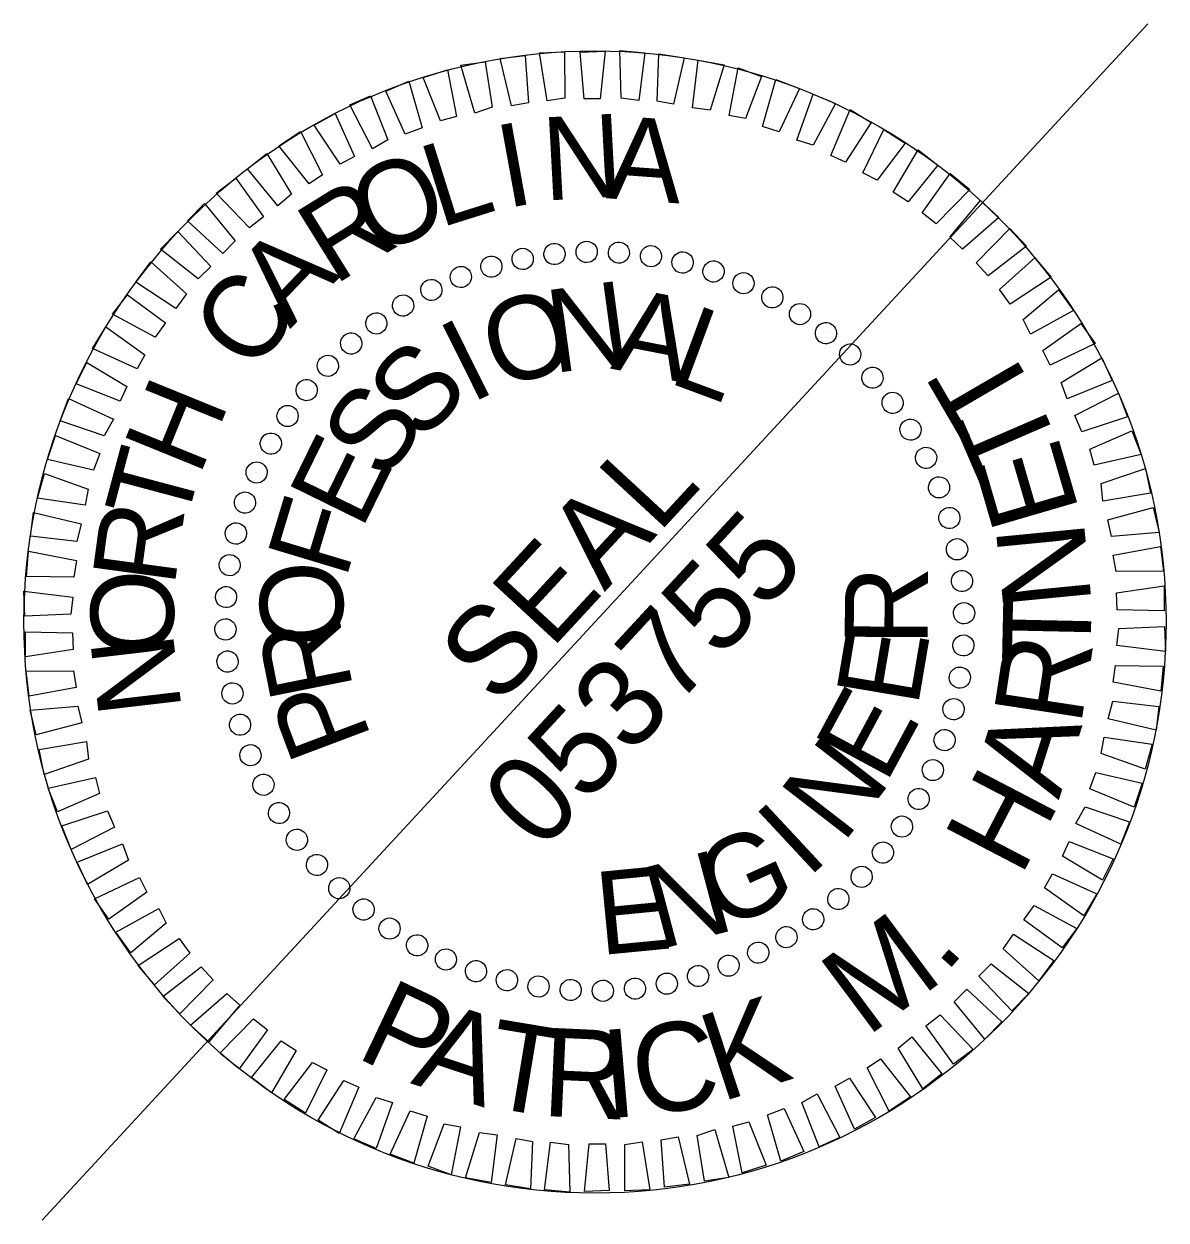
# Model space of a CAD drawing. Extents: x 1768274 to 1769121, y 999922 to 1000687.
# Drawn here: x 1769002.478 to 1769003.66, y 1000309.793 to 1000311.03 of the extents above; entities that cross this region are included whole.
import ezdxf

# ---------------------------------------------------------------- set-up
doc = ezdxf.new("R2010")
doc.units = 0
doc.layers.add('E_NCDOT_Terrain_Model_Contour_Imported', color=7, linetype='Continuous')
doc.layers.add('E_NCDOT_Terrain_Model_Void', color=7, linetype='Continuous')

msp = doc.modelspace()

# ---------------------------------------------------------------- linework, layer by layer
at = {"layer": 'E_NCDOT_Terrain_Model_Contour_Imported'}
msp.add_line((1769003.6407, 1000311.0298), (1769002.4971, 1000309.7927), dxfattribs=at)
msp.add_circle((1769003.0689, 1000310.4113), 0.5907, dxfattribs=at)
at = {"layer": 'E_NCDOT_Terrain_Model_Void'}
for p, q in [((1769002.9941, 1000310.7869), (1769002.9941, 1000310.7869)), ((1769003.0273, 1000310.7926), (1769003.0273, 1000310.7926)), ((1769003.0601, 1000310.7944), (1769003.0601, 1000310.7944)), ((1769003.0941, 1000310.7941), (1769003.0941, 1000310.7941)), ((1769003.1266, 1000310.79), (1769003.1266, 1000310.79)), ((1769003.1597, 1000310.7832), (1769003.1597, 1000310.7832)), ((1769002.9615, 1000310.7797), (1769002.9615, 1000310.7797)), ((1769003.1919, 1000310.7742), (1769003.1919, 1000310.7742)), ((1769002.9301, 1000310.7683), (1769002.9301, 1000310.7683)), ((1769003.2225, 1000310.7625), (1769003.2225, 1000310.7625)), ((1769002.8993, 1000310.7552), (1769002.8993, 1000310.7552)), ((1769003.2522, 1000310.7475), (1769003.2522, 1000310.7475)), ((1769002.8698, 1000310.7389), (1769002.8698, 1000310.7389)), ((1769003.281, 1000310.7292), (1769003.281, 1000310.7292)), ((1769002.843, 1000310.7201), (1769002.843, 1000310.7201)), ((1769003.3081, 1000310.7103), (1769003.3081, 1000310.7103)), ((1769002.8169, 1000310.6997), (1769002.8169, 1000310.6997)), ((1769003.3333, 1000310.6881), (1769003.3333, 1000310.6881)), ((1769002.7925, 1000310.6766), (1769002.7925, 1000310.6766)), ((1769003.3563, 1000310.6637), (1769003.3563, 1000310.6637)), ((1769002.7703, 1000310.6515), (1769002.7703, 1000310.6515)), ((1769003.3768, 1000310.6376), (1769003.3768, 1000310.6376)), ((1769002.7514, 1000310.6243), (1769002.7514, 1000310.6243)), ((1769003.3956, 1000310.6108), (1769003.3956, 1000310.6108)), ((1769002.7331, 1000310.5955), (1769002.7331, 1000310.5955)), ((1769003.4119, 1000310.5813), (1769003.4119, 1000310.5813)), ((1769002.7181, 1000310.5658), (1769002.7181, 1000310.5658)), ((1769003.4249, 1000310.5505), (1769003.4249, 1000310.5505)), ((1769002.7064, 1000310.5352), (1769002.7064, 1000310.5352)), ((1769003.4364, 1000310.5192), (1769003.4364, 1000310.5192)), ((1769002.6974, 1000310.503), (1769002.6974, 1000310.503)), ((1769003.4436, 1000310.4865), (1769003.4436, 1000310.4865)), ((1769002.6906, 1000310.4699), (1769002.6906, 1000310.4699)), ((1769003.4492, 1000310.4533), (1769003.4492, 1000310.4533)), ((1769002.6865, 1000310.4374), (1769002.6865, 1000310.4374)), ((1769003.4511, 1000310.4205), (1769003.4511, 1000310.4205)), ((1769002.6862, 1000310.4034), (1769002.6862, 1000310.4034)), ((1769003.0686, 1000310.412), (1769003.0686, 1000310.412)), ((1769003.4508, 1000310.3866), (1769003.4508, 1000310.3866)), ((1769002.688, 1000310.3706), (1769002.688, 1000310.3706)), ((1769003.4467, 1000310.354), (1769003.4467, 1000310.354)), ((1769002.6937, 1000310.3374), (1769002.6937, 1000310.3374)), ((1769003.4399, 1000310.3209), (1769003.4399, 1000310.3209)), ((1769002.7009, 1000310.3048), (1769002.7009, 1000310.3048)), ((1769003.4309, 1000310.2887), (1769003.4309, 1000310.2887)), ((1769002.7124, 1000310.2734), (1769002.7124, 1000310.2734)), ((1769003.4192, 1000310.2581), (1769003.4192, 1000310.2581)), ((1769002.7254, 1000310.2427), (1769002.7254, 1000310.2427)), ((1769003.4042, 1000310.2284), (1769003.4042, 1000310.2284)), ((1769002.7417, 1000310.2131), (1769002.7417, 1000310.2131)), ((1769003.3859, 1000310.1996), (1769003.3859, 1000310.1996)), ((1769002.7605, 1000310.1864), (1769002.7605, 1000310.1864)), ((1769003.367, 1000310.1725), (1769003.367, 1000310.1725)), ((1769002.781, 1000310.1602), (1769002.781, 1000310.1602)), ((1769003.3448, 1000310.1473), (1769003.3448, 1000310.1473)), ((1769002.804, 1000310.1358), (1769002.804, 1000310.1358)), ((1769003.3204, 1000310.1243), (1769003.3204, 1000310.1243)), ((1769002.8291, 1000310.1136), (1769002.8291, 1000310.1136)), ((1769003.2942, 1000310.1038), (1769003.2942, 1000310.1038)), ((1769002.8563, 1000310.0947), (1769002.8563, 1000310.0947)), ((1769003.2675, 1000310.085), (1769003.2675, 1000310.085)), ((1769002.8851, 1000310.0764), (1769002.8851, 1000310.0764)), ((1769003.2379, 1000310.0687), (1769003.2379, 1000310.0687)), ((1769002.9148, 1000310.0614), (1769002.9148, 1000310.0614)), ((1769003.2072, 1000310.0557), (1769003.2072, 1000310.0557)), ((1769002.9454, 1000310.0497), (1769002.9454, 1000310.0497)), ((1769003.1758, 1000310.0442), (1769003.1758, 1000310.0442)), ((1769002.9776, 1000310.0407), (1769002.9776, 1000310.0407)), ((1769003.0107, 1000310.0339), (1769003.0107, 1000310.0339)), ((1769003.0432, 1000310.0298), (1769003.0432, 1000310.0298)), ((1769003.0772, 1000310.0295), (1769003.0772, 1000310.0295)), ((1769003.11, 1000310.0314), (1769003.11, 1000310.0314)), ((1769003.1432, 1000310.037), (1769003.1432, 1000310.037))]:
    msp.add_line(p, q, dxfattribs=at)
for points in [[(1769002.9825, 1000310.945), (1769002.9708, 1000310.9941), (1769002.9966, 1000310.9973), (1769003.0001, 1000310.9484)], [(1769003.0194, 1000310.9502), (1769003.0116, 1000311), (1769003.0374, 1000311.0011), (1769003.0377, 1000310.9531)], [(1769003.0576, 1000310.9523), (1769003.0536, 1000311.0006), (1769003.0794, 1000311.0016), (1769003.0744, 1000310.9524)], [(1769003.0959, 1000310.9532), (1769003.0945, 1000311.0022), (1769003.1205, 1000311), (1769003.1143, 1000310.9507)], [(1769003.1332, 1000310.9498), (1769003.1351, 1000310.999), (1769003.1611, 1000310.9946), (1769003.15, 1000310.9467)], [(1769002.9092, 1000310.9297), (1769002.8913, 1000310.9743), (1769002.9163, 1000310.9823), (1769002.9257, 1000310.9341)], [(1769002.9445, 1000310.9376), (1769002.9301, 1000310.9871), (1769002.9553, 1000310.9908), (1769002.9626, 1000310.9437)], [(1769003.1696, 1000310.9432), (1769003.1757, 1000310.9925), (1769003.2024, 1000310.9876), (1769003.188, 1000310.9407)], [(1769003.2077, 1000310.935), (1769003.217, 1000310.9844), (1769003.2411, 1000310.9756), (1769003.2245, 1000310.9319)], [(1769002.8725, 1000310.9159), (1769002.8525, 1000310.9604), (1769002.8763, 1000310.9705), (1769002.8901, 1000310.9225)], [(1769003.2421, 1000310.9239), (1769003.2558, 1000310.9724), (1769003.2804, 1000310.9632), (1769003.2595, 1000310.9181)], [(1769003.2777, 1000310.9097), (1769003.2947, 1000310.9573), (1769003.3177, 1000310.9474), (1769003.2946, 1000310.9044)], [(1769002.8386, 1000310.9005), (1769002.8153, 1000310.946), (1769002.8365, 1000310.9554), (1769002.8545, 1000310.9098)], [(1769002.8053, 1000310.8847), (1769002.7784, 1000310.9251), (1769002.8, 1000310.9373), (1769002.8201, 1000310.8928)], [(1769003.3128, 1000310.8938), (1769003.333, 1000310.9415), (1769003.3546, 1000310.9278), (1769003.3281, 1000310.8869)], [(1769003.3458, 1000310.8757), (1769003.3678, 1000310.9208), (1769003.3899, 1000310.9066), (1769003.3607, 1000310.8682)], [(1769002.7732, 1000310.8645), (1769002.742, 1000310.9037), (1769002.7641, 1000310.9186), (1769002.7869, 1000310.8737)], [(1769002.7407, 1000310.8417), (1769002.7095, 1000310.8798), (1769002.7294, 1000310.8957), (1769002.7548, 1000310.8536)], [(1769003.3773, 1000310.8559), (1769003.4031, 1000310.8995), (1769003.4237, 1000310.8836), (1769003.3928, 1000310.8458)], [(1769002.7114, 1000310.819), (1769002.6771, 1000310.8548), (1769002.6975, 1000310.8702), (1769002.726, 1000310.8303)], [(1769003.4073, 1000310.8345), (1769003.4364, 1000310.875), (1769003.4565, 1000310.8585), (1769003.4218, 1000310.8232)], [(1769003.4358, 1000310.8092), (1769003.4677, 1000310.8471), (1769003.4867, 1000310.8295), (1769003.4492, 1000310.7968)], [(1769002.6839, 1000310.7925), (1769002.6475, 1000310.8262), (1769002.6651, 1000310.8441), (1769002.6968, 1000310.8055)], [(1769002.6585, 1000310.7662), (1769002.6195, 1000310.797), (1769002.6372, 1000310.815), (1769002.6714, 1000310.7791)], [(1769003.4632, 1000310.7827), (1769003.498, 1000310.8181), (1769003.5154, 1000310.7999), (1769003.4756, 1000310.7692)], [(1769002.6354, 1000310.7356), (1769002.5939, 1000310.7626), (1769002.6093, 1000310.7837), (1769002.6462, 1000310.7506)], [(1769003.4875, 1000310.7551), (1769003.524, 1000310.7878), (1769003.5409, 1000310.768), (1769003.4984, 1000310.7399)], [(1769002.614, 1000310.7057), (1769002.5699, 1000310.7298), (1769002.5853, 1000310.7498), (1769002.6247, 1000310.7207)], [(1769003.5119, 1000310.7243), (1769003.5484, 1000310.7548), (1769003.5638, 1000310.7333), (1769003.5195, 1000310.7089)], [(1769002.5953, 1000310.6732), (1769002.5492, 1000310.694), (1769002.5628, 1000310.7166), (1769002.6033, 1000310.6875)], [(1769003.532, 1000310.6922), (1769003.5714, 1000310.7201), (1769003.5862, 1000310.6992), (1769003.5396, 1000310.6769)], [(1769003.5511, 1000310.659), (1769003.5933, 1000310.6844), (1769003.6039, 1000310.661), (1769003.5572, 1000310.642)], [(1769002.5777, 1000310.6396), (1769002.5323, 1000310.6577), (1769002.5433, 1000310.6797), (1769002.5847, 1000310.6549)], [(1769003.5654, 1000310.625), (1769003.6103, 1000310.6478), (1769003.6199, 1000310.6234), (1769003.5725, 1000310.6081)], [(1769002.5613, 1000310.6039), (1769002.5155, 1000310.6193), (1769002.5243, 1000310.6423), (1769002.5709, 1000310.621)], [(1769002.5503, 1000310.5684), (1769002.5025, 1000310.5795), (1769002.5107, 1000310.6041), (1769002.5567, 1000310.5854)], [(1769003.5808, 1000310.5901), (1769003.6243, 1000310.609), (1769003.6338, 1000310.5846), (1769003.5852, 1000310.5735)], [(1769002.5415, 1000310.532), (1769002.4922, 1000310.5392), (1769002.4993, 1000310.5648), (1769002.5446, 1000310.5488)], [(1769003.5924, 1000310.5544), (1769003.6382, 1000310.5702), (1769003.6435, 1000310.5445), (1769003.5942, 1000310.5361)], [(1769002.5328, 1000310.4944), (1769002.4851, 1000310.5001), (1769002.4879, 1000310.5245), (1769002.5374, 1000310.5129)], [(1769003.5993, 1000310.5169), (1769003.6462, 1000310.5296), (1769003.6526, 1000310.5039), (1769003.6032, 1000310.4998)], [(1769003.605, 1000310.4805), (1769003.6538, 1000310.4894), (1769003.6569, 1000310.4637), (1769003.6079, 1000310.4634)], [(1769002.5299, 1000310.4576), (1769002.4808, 1000310.4584), (1769002.483, 1000310.4844), (1769002.5325, 1000310.475)], [(1769002.5266, 1000310.4192), (1769002.4792, 1000310.4174), (1769002.4782, 1000310.4432), (1769002.5286, 1000310.4371)], [(1769003.6082, 1000310.4413), (1769003.6575, 1000310.4486), (1769003.6575, 1000310.4227), (1769003.6089, 1000310.424)], [(1769002.5291, 1000310.3827), (1769002.4798, 1000310.3753), (1769002.4798, 1000310.4012), (1769002.5284, 1000310.3999)], [(1769003.6107, 1000310.4047), (1769003.6581, 1000310.4066), (1769003.6591, 1000310.3807), (1769003.6087, 1000310.3868)], [(1769003.6074, 1000310.3663), (1769003.6565, 1000310.3655), (1769003.6543, 1000310.3396), (1769003.6048, 1000310.3489)], [(1769002.5322, 1000310.3434), (1769002.4835, 1000310.3345), (1769002.4804, 1000310.3603), (1769002.5294, 1000310.3606)], [(1769003.6045, 1000310.3295), (1769003.6522, 1000310.3239), (1769003.6494, 1000310.2995), (1769003.5999, 1000310.311)], [(1769002.538, 1000310.307), (1769002.491, 1000310.2944), (1769002.4846, 1000310.32), (1769002.5341, 1000310.3241)], [(1769003.5957, 1000310.292), (1769003.6451, 1000310.2848), (1769003.638, 1000310.2591), (1769003.5926, 1000310.2751)], [(1769002.5448, 1000310.2695), (1769002.4991, 1000310.2537), (1769002.4938, 1000310.2794), (1769002.543, 1000310.2878)], [(1769003.5869, 1000310.2555), (1769003.6348, 1000310.2445), (1769003.6266, 1000310.2199), (1769003.5806, 1000310.2386)], [(1769002.5565, 1000310.2339), (1769002.513, 1000310.2149), (1769002.5034, 1000310.2393), (1769002.5521, 1000310.2504)], [(1769002.5719, 1000310.1989), (1769002.527, 1000310.1761), (1769002.5174, 1000310.2005), (1769002.5647, 1000310.2159)], [(1769003.5759, 1000310.22), (1769003.6218, 1000310.2046), (1769003.613, 1000310.1816), (1769003.5664, 1000310.203)], [(1769002.5862, 1000310.165), (1769002.544, 1000310.1396), (1769002.5334, 1000310.1629), (1769002.5801, 1000310.182)], [(1769003.5595, 1000310.1844), (1769003.605, 1000310.1662), (1769003.594, 1000310.1442), (1769003.5526, 1000310.169)], [(1769002.6052, 1000310.1317), (1769002.5659, 1000310.1038), (1769002.5511, 1000310.1248), (1769002.5976, 1000310.1471)], [(1769003.542, 1000310.1508), (1769003.5881, 1000310.13), (1769003.5744, 1000310.1073), (1769003.5339, 1000310.1364)], [(1769003.5233, 1000310.1182), (1769003.5674, 1000310.0941), (1769003.552, 1000310.0741), (1769003.5126, 1000310.1033)], [(1769002.6254, 1000310.0997), (1769002.5888, 1000310.0691), (1769002.5734, 1000310.0906), (1769002.6178, 1000310.115)], [(1769002.6498, 1000310.0688), (1769002.6133, 1000310.0361), (1769002.5964, 1000310.0559), (1769002.6389, 1000310.084)], [(1769003.5019, 1000310.0883), (1769003.5434, 1000310.0613), (1769003.528, 1000310.0403), (1769003.4911, 1000310.0733)], [(1769002.674, 1000310.0412), (1769002.6393, 1000310.0059), (1769002.6219, 1000310.024), (1769002.6616, 1000310.0547)], [(1769003.4788, 1000310.0577), (1769003.5178, 1000310.0269), (1769003.5001, 1000310.009), (1769003.4658, 1000310.0448)], [(1769003.4534, 1000310.0314), (1769003.4898, 1000309.9978), (1769003.4722, 1000309.9798), (1769003.4405, 1000310.0185)], [(1769002.7015, 1000310.0148), (1769002.6696, 1000309.9769), (1769002.6505, 1000309.9944), (1769002.6881, 1000310.0272)], [(1769003.4259, 1000310.005), (1769003.4602, 1000309.9691), (1769003.4398, 1000309.9538), (1769003.4112, 1000309.9936)], [(1769002.73, 1000309.9895), (1769002.7008, 1000309.949), (1769002.6808, 1000309.9654), (1769002.7155, 1000310.0008)], [(1769003.3966, 1000309.9823), (1769003.4277, 1000309.9441), (1769003.4079, 1000309.9283), (1769003.3825, 1000309.9704)], [(1769002.7599, 1000309.968), (1769002.7342, 1000309.9244), (1769002.7136, 1000309.9403), (1769002.7444, 1000309.9782)], [(1769002.7914, 1000309.9482), (1769002.7695, 1000309.9032), (1769002.7474, 1000309.9174), (1769002.7766, 1000309.9557)], [(1769003.3641, 1000309.9594), (1769003.3953, 1000309.9202), (1769003.3732, 1000309.9053), (1769003.3504, 1000309.9503)], [(1769002.8245, 1000309.9301), (1769002.8043, 1000309.8824), (1769002.7827, 1000309.8961), (1769002.8091, 1000309.9371)], [(1769003.332, 1000309.9393), (1769003.3589, 1000309.8988), (1769003.3373, 1000309.8867), (1769003.3172, 1000309.9312)], [(1769002.8596, 1000309.9142), (1769002.8426, 1000309.8667), (1769002.8196, 1000309.8766), (1769002.8427, 1000309.9195)], [(1769003.2986, 1000309.9234), (1769003.322, 1000309.878), (1769003.3008, 1000309.8685), (1769003.2828, 1000309.9142)], [(1769002.8952, 1000309.9), (1769002.8815, 1000309.8515), (1769002.8569, 1000309.8608), (1769002.8778, 1000309.9058)], [(1769003.2647, 1000309.9081), (1769003.2848, 1000309.8636), (1769003.261, 1000309.8535), (1769003.2472, 1000309.9014)], [(1769003.2281, 1000309.8942), (1769003.246, 1000309.8496), (1769003.221, 1000309.8417), (1769003.2115, 1000309.8898)], [(1769002.9296, 1000309.889), (1769002.9202, 1000309.8395), (1769002.8962, 1000309.8483), (1769002.9128, 1000309.8921)], [(1769002.9677, 1000309.8808), (1769002.9615, 1000309.8315), (1769002.9349, 1000309.8363), (1769002.9493, 1000309.8833)], [(1769003.1928, 1000309.8864), (1769003.2072, 1000309.8368), (1769003.182, 1000309.8331), (1769003.1747, 1000309.8803)], [(1769003.0041, 1000309.8741), (1769003.0022, 1000309.825), (1769002.9762, 1000309.8293), (1769002.9872, 1000309.8772)], [(1769003.0414, 1000309.8707), (1769003.0428, 1000309.8217), (1769003.0168, 1000309.8239), (1769003.023, 1000309.8732)], [(1769003.0796, 1000309.8717), (1769003.0837, 1000309.8233), (1769003.0579, 1000309.8223), (1769003.0629, 1000309.8716)], [(1769003.1178, 1000309.8737), (1769003.1257, 1000309.8239), (1769003.0999, 1000309.8229), (1769003.0996, 1000309.8708)], [(1769003.1548, 1000309.8789), (1769003.1665, 1000309.8298), (1769003.1407, 1000309.8266), (1769003.1372, 1000309.8756)]]:
    msp.add_lwpolyline(points, close=True, dxfattribs=at)
for centre, major_axis in [((1769002.9941, 1000310.7868), (-0.0021, 0.0108)), ((1769003.027, 1000310.7918), (-0.0012, 0.0109)), ((1769003.0603, 1000310.794), (-0.0002, 0.011)), ((1769003.0936, 1000310.7933), (0.0007, 0.0109)), ((1769003.1268, 1000310.7896), (0.0017, 0.0108)), ((1769002.9617, 1000310.7788), (-0.0031, 0.0105)), ((1769003.1595, 1000310.7831), (0.0026, 0.0107)), ((1769003.1915, 1000310.7738), (0.0035, 0.0104)), ((1769002.9301, 1000310.7681), (-0.004, 0.0102)), ((1769003.2225, 1000310.7617), (0.0044, 0.01)), ((1769002.8996, 1000310.7547), (-0.00485, 0.00984)), ((1769003.2524, 1000310.747), (0.00528, 0.00962)), ((1769002.8704, 1000310.7386), (-0.00569, 0.00938)), ((1769003.2809, 1000310.7297), (0.00609, 0.00912)), ((1769002.8427, 1000310.7201), (-0.00649, 0.00885)), ((1769003.3078, 1000310.71), (0.00687, 0.00856)), ((1769002.8167, 1000310.6993), (-0.00723, 0.00825)), ((1769003.3329, 1000310.688), (0.00759, 0.00792)), ((1769002.7926, 1000310.6762), (-0.00792, 0.00759)), ((1769003.3559, 1000310.6639), (0.00825, 0.00723)), ((1769002.7706, 1000310.6511), (-0.00856, 0.00687)), ((1769003.3768, 1000310.6379), (0.00885, 0.00649)), ((1769002.7509, 1000310.6243), (-0.00912, 0.00609)), ((1769003.3953, 1000310.6102), (0.00938, 0.00569)), ((1769002.7336, 1000310.5958), (-0.00962, 0.00528)), ((1769003.4114, 1000310.581), (0.00984, 0.00485)), ((1769002.7189, 1000310.5659), (-0.01, 0.0044)), ((1769003.4248, 1000310.5505), (0.0102, 0.004)), ((1769002.7068, 1000310.5348), (-0.0104, 0.0035)), ((1769003.4355, 1000310.5189), (0.0105, 0.0031)), ((1769002.6975, 1000310.5028), (-0.0107, 0.0026)), ((1769003.4434, 1000310.4865), (0.0108, 0.0021)), ((1769002.691, 1000310.4701), (-0.0108, 0.0017)), ((1769003.4485, 1000310.4536), (0.0109, 0.0012)), ((1769002.6873, 1000310.437), (-0.0109, 0.0007)), ((1769003.4507, 1000310.4203), (0.011, 0.0002)), ((1769002.6866, 1000310.4036), (-0.011, -0.0002)), ((1769003.45, 1000310.387), (0.0109, -0.0007)), ((1769002.6888, 1000310.3704), (-0.0109, -0.0012)), ((1769003.4463, 1000310.3538), (0.0108, -0.0017)), ((1769002.6939, 1000310.3374), (-0.0108, -0.0021)), ((1769003.4398, 1000310.3211), (0.0107, -0.0026)), ((1769002.7018, 1000310.305), (-0.0105, -0.0031)), ((1769003.4305, 1000310.2891), (0.0104, -0.0035)), ((1769002.7125, 1000310.2735), (-0.0102, -0.004)), ((1769003.4184, 1000310.2581), (0.01, -0.0044)), ((1769002.7259, 1000310.2429), (-0.00984, -0.00485)), ((1769003.4037, 1000310.2282), (0.00962, -0.00528)), ((1769002.742, 1000310.2137), (-0.00938, -0.00569)), ((1769003.3864, 1000310.1997), (0.00912, -0.00609)), ((1769002.7605, 1000310.186), (-0.00885, -0.00649)), ((1769003.3667, 1000310.1728), (0.00856, -0.00687)), ((1769002.7813, 1000310.16), (-0.00825, -0.00723)), ((1769003.3447, 1000310.1477), (0.00792, -0.00759)), ((1769002.8044, 1000310.1359), (-0.00759, -0.00792)), ((1769003.3206, 1000310.1247), (0.00723, -0.00825)), ((1769002.8295, 1000310.1139), (-0.00687, -0.00856)), ((1769003.2946, 1000310.1038), (0.00649, -0.00885)), ((1769002.8564, 1000310.0942), (-0.00609, -0.00912)), ((1769003.2669, 1000310.0853), (0.00569, -0.00938)), ((1769002.8849, 1000310.0769), (-0.00528, -0.00962)), ((1769003.2377, 1000310.0693), (0.00485, -0.00984)), ((1769002.9147, 1000310.0622), (-0.0044, -0.01)), ((1769003.2071, 1000310.0558), (0.004, -0.0102)), ((1769002.9458, 1000310.0501), (-0.0035, -0.0104)), ((1769003.1756, 1000310.0451), (0.0031, -0.0105)), ((1769002.9778, 1000310.0408), (-0.0026, -0.0107)), ((1769003.0105, 1000310.0343), (-0.0017, -0.0108)), ((1769003.0437, 1000310.0307), (-0.0007, -0.0109)), ((1769003.077, 1000310.0299), (0.0002, -0.011)), ((1769003.1103, 1000310.0321), (0.0012, -0.0109)), ((1769003.1432, 1000310.0372), (0.0021, -0.0108))]:
    msp.add_ellipse(centre, major_axis=major_axis, ratio=0.999708, dxfattribs=at)

# ---------------------------------------------------------------- texts
for s, height, rotation, p in [('N', 0.0859, 3.0701, (1769003.0165, 1000310.8471)), ('A', 0.0859, 355.8684, (1769003.08, 1000310.8496)), ('I', 0.0859, 10.2714, (1769002.9769, 1000310.8391)), ('L', 0.0859, 17.4721, (1769002.9082, 1000310.8186)), ('O', 0.0859, 24.6724, (1769002.842, 1000310.7885)), ('R', 0.0859, 31.8723, (1769002.7989, 1000310.7588)), ('A', 0.0859, 46.2715, (1769002.7533, 1000310.7139)), ('C', 0.0859, 53.4711, (1769002.7158, 1000310.6666)), ('N', 0.0859, 7.7278, (1769003.0257, 1000310.6685)), ('O', 0.0859, 17.0847, (1769002.9686, 1000310.6517)), ('A', 0.0859, 349.0115, (1769003.0842, 1000310.6735)), ('L', 0.0859, 339.6521, (1769003.143, 1000310.6596)), ('I', 0.0859, 26.4408, (1769002.9401, 1000310.6366)), ('S', 0.0859, 45.1516, (1769002.8878, 1000310.5957)), ('T', 0.0914, 120.207, (1769003.5284, 1000310.6428)), ('H', 0.0859, 67.8707, (1769002.6595, 1000310.5608)), ('S', 0.0859, 54.5068, (1769002.8512, 1000310.5549)), ('T', 0.0914, 113.4067, (1769003.5525, 1000310.5867)), ('E', 0.0859, 63.8623, (1769002.8272, 1000310.5054)), ('E', 0.0914, 106.2974, (1769003.5704, 1000310.5255)), ('T', 0.0859, 75.071, (1769002.6444, 1000310.5074)), ('SEAL', 0.09139, 47.2512, (1769002.9681, 1000310.3223)), ('F', 0.0859, 73.2183, (1769002.8109, 1000310.4541)), ('R', 0.0859, 82.2717, (1769002.6338, 1000310.4466)), ('053755', 0.09139, 47.2512, (1769003.0131, 1000310.1721)), ('N', 0.0914, 95.5715, (1769003.5828, 1000310.4301)), ('O', 0.0859, 91.9325, (1769002.8098, 1000310.3867)), ('R', 0.0859, 89.7326, (1769003.4131, 1000310.3862)), ('O', 0.0859, 89.473, (1769002.6328, 1000310.376)), ('T', 0.0914, 88.7713, (1769003.5813, 1000310.3691)), ('R', 0.0859, 101.2909, (1769002.8191, 1000310.3418)), ('E', 0.0859, 80.3753, (1769003.4026, 1000310.3221)), ('N', 0.0859, 96.6747, (1769002.6415, 1000310.3202)), ('R', 0.0914, 81.291, (1769003.5714, 1000310.3027)), ('P', 0.0859, 110.6501, (1769002.8384, 1000310.2908)), ('E', 0.0859, 61.663, (1769003.3696, 1000310.2427)), ('A', 0.0914, 72.4507, (1769003.5486, 1000310.2268)), ('N', 0.0859, 52.3076, (1769003.3252, 1000310.1811)), ('H', 0.0914, 62.4668, (1769003.5092, 1000310.1464)), ('I', 0.0859, 42.9524, (1769003.2888, 1000310.1451)), ('G', 0.0859, 24.2415, (1769003.1998, 1000310.0915)), ('N', 0.0859, 14.8852, (1769003.1354, 1000310.0723)), ('E', 0.0859, 5.5281, (1769003.0741, 1000310.0666)), ('M', 0.0914, 36.7031, (1769003.35, 1000309.9813)), ('.', 0.0914, 48.2326, (1769003.4304, 1000310.0462)), ('P', 0.0914, 334.6046, (1769002.8197, 1000309.9618)), ('K', 0.0914, 18.2189, (1769003.1989, 1000309.9143)), ('A', 0.0914, 341.7139, (1769002.8773, 1000309.9344)), ('T', 0.0914, 350.5543, (1769002.9529, 1000309.9107)), ('C', 0.0914, 8.6367, (1769003.1143, 1000309.8995)), ('R', 0.0914, 357.3545, (1769003.0131, 1000309.9005)), ('I', 0.0914, 4.8347, (1769003.0802, 1000309.8976))]:
    msp.add_text(s, height=height, rotation=rotation, dxfattribs=at).set_placement(p)

doc.saveas('drawing.dxf')
